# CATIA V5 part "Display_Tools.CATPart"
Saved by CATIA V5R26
Part number: Display_Tools
Bounding box of the stored display mesh (mm): x 864.508 to 1402.538, y -729.458 to -658.95, z 407.954 to 547.921
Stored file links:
  D:\LinkedIn Learning\NURBS\CATIA\Class Parts\Display_Tools.CATPart
  D:\LinkedIn Learning\NURBS\CATIA\Class Parts\Arm_Rest-Step-2.CATPart
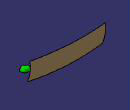
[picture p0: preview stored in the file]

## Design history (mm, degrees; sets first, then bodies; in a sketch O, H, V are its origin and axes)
AxisSystem1: origin (0, 0, 0), X (1, 0, 0), Y (0, 1, 0), Z (0, 0, 1)
Set1
  DatumSurface1
  DatumSurface2
Body1 (main body)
